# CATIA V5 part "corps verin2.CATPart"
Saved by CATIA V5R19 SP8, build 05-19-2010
Part number: corps verin2
Bounding box of the stored display mesh (mm): x 1.043 to 52.728, y 45 to 55.403, z 75.546 to 157.988
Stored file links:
  G:\EU_thinkMotion\CFAO_2010\MMS_groupe1\MMS_groupe1\A reprendre\OK\glenerrant\glenerrant\glenerrant\corps verin2.CATPart
  G:\EU_thinkMotion\CFAO_2010\MMS_groupe1\MMS_groupe1\A reprendre\OK\glenerrant\glenerrant\glenerrant\Tige verin2.CATPart
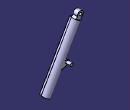
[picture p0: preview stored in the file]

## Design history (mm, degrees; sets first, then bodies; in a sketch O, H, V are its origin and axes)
Parameters
  `Longueur coprs verin 2` = 88 mm
Set1
  Point1: (5, 51, 154)
  Point2: (89, 51, 8)
  Point3: (5, -51, 154)
  Line1: type PtPt, FirstPoint Point1, SecondPoint Point2
  Line2: type PtPt, FirstPoint Point1, SecondPoint Point3
  Plane1: type Normal, Curve Line1, RefPoint Point1
  Plane2: type Normal, Curve Line2, RefPoint Point1
  Point4: (17, 51, 101)
Body1 (main body)
  Sketch1 on Plane2, origin (0, 51, 0), H (1, 0, 0), V (0, 0, 1)
    arc A1 centre (5, 154) radius 4 from (8.8226, 152.8221) to (4.097, 150.1033) ccw
    point P1 (5, 154)
    reference projected point E1 (5, 154) from Point1
    line L1 (8.8226, 152.8221) -> (11.8927, 151.0435)
    line L2 (4.097, 150.1033) -> (4.0917, 146.5552)
    point P5 (4.0917, 146.5552)
    line L3 (4.0917, 146.5552) -> (11.8927, 151.0435)
    reference intersected line E2 through (-65.3241, 113.5395) direction (0.8668, 0.4987) from Plane1
    reference projected point E3 (5, 154) from Point1
    reference projected line E4 (5, 154) -> (89, 8) from Line1
    circle A2 centre (5, 154) radius 2
    point P6 (5, 154)
    reference projected point E5 (5, 154) from Point1
    radius A1 = 4
    distance L3 E3 = 6
    length L3 = 9
    angle L2 L3 = 60
    angle L1 L3 = 60
    distance P5 E4 = 4.5
    radius A2 = 2
    coincidence: P1 E1, P6 E5
    parallelism: E2 L3
  Pad1: profile Sketch1, direction (0, -1, 0), length 3, opposite side length 3
  Sketch2 on Plane1, origin (-65.3241, 0, 113.5395), H (0, 1, 0), V (0.8668, 0, 0.4987)
    line L1 (45, 82.4315) -> (45, 83.9315)
    line L2 (45, 77.9315) -> (45, 79.4315)
    point P3 (45, 77.9315)
    line L3 (45, 77.9315) -> (47.8374, 77.9315)
    line L4 (45, 82.4315) -> (47, 82.4315)
    line L5 (45, 83.9315) -> (47.4762, 83.9315)
    line L6 (45, 79.4315) -> (47, 79.4315)
    line L7 (47, 82.4315) -> (47, 79.4315)
    reference projected point E1 (51, 81.1328) from Point1
    reference projected point E2 (51, 81.1328) from Point5
    arc A1 centre (51, 81.1328) radius 4.5 from (47.8374, 77.9315) to (47.4762, 83.9315) ccw
    point P9 (51, 81.1328)
    reference projected point E3 (51, 81.1328) from Point1
    length L4 = 2
    length L6 = 2
    distance L2 E1 = 6
    distance L6 L4 = 3
    distance L3 L6 = 1.5
    distance L4 L5 = 1.5
    distance L6 E2 = 1.7013
    radius A1 = 4.5
    vertical: L1 V, L2 V
    coincidence: P3 L1, P9 E3
    horizontal: L3 H, L4 H, L5 H, L6 H
  Pad2: profile Sketch2, direction (0.4987, 0, -0.8668), length 88, opposite side length -6
  Sketch3 on end face of Pad2, origin (48.8851, 51, 77.7235), H (0.8668, 0, 0.4987), V (0, -1, 0)
    point P1 (0, 0)
  Hole1: placed by Sketch3, at (48.8851, 51, 77.7235) direction (-0.4987, 0, 0.8668), diameter 5, depth 80
  Sketch4 on face of Pad2 from Sketch2.L2, origin (0, 45, 0), H (1, 0, 0), V (0, 0, 1)
    line L1 (36.5877, 92.6782) -> (16.2279, 98.1011)
    line L2 (36.5877, 92.6782) -> (29.1073, 105.6798)
    point P3 (29.1073, 105.6798)
    line L3 (29.1073, 105.6798) -> (16.5944, 103.9725)
    point P4 (29.1073, 105.6798)
    arc A1 centre (17, 101) radius 3 from (16.5944, 103.9725) to (16.2279, 98.1011) ccw
    point P6 (17, 101)
    reference projected point E1 (17, 101) from Point4
    reference projected line E2 (5, 154) -> (89, 8) from Line1
    reference projected point E3 (5, 154) from Point1
    reference projected line E4 (5.2174, 147.2029) -> (46.1103, 76.1271) from edge [face of Pad2 from Sketch2.L3 | face of Pad2 from Sketch2.L2]
    radius A1 = 3
    distance P3 E3 = 54
    length L2 = 15
    coincidence: P4 L2, P6 E1, P4 P3, E4 L2
    tangency: L1 A1, L3 A1
    parallelism: E2 L2
  Pad3: profile Sketch4, direction (0, 1, 0), length 3
  Point5: stored without definition
  Sketch5 on end face of Pad3, origin (0, 48, 0), H (-1, 0, 0), V (0, 0, 1)
    circle A1 centre (-17, 101) radius 2
    point P1 (-17, 101)
    reference projected point E1 (-17, 101) from Point4
    radius A1 = 2
    coincidence: P1 E1
  Pad4: profile Sketch5, direction (0, 1, 0), length 6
